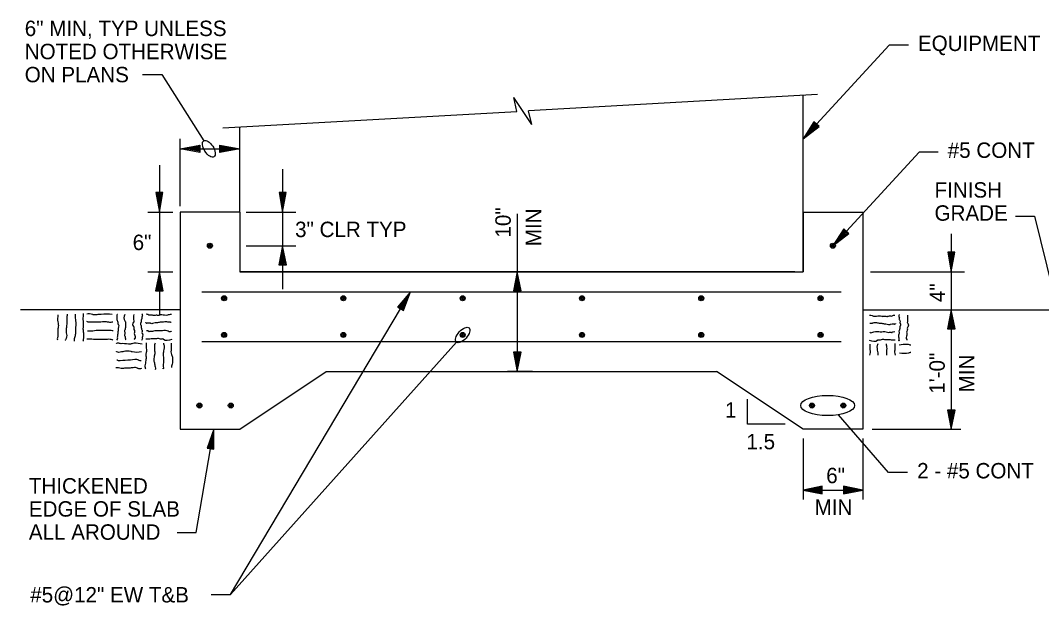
# Model space of a CAD drawing. Extents: x -123486 to -116575, y -107066 to -101122.
# Drawn here: x -118359.2 to -117961.3, y -101555.2 to -101327.3 of the extents above; entities that cross this region are included whole.
import ezdxf

# ---------------------------------------------------------------- set-up
doc = ezdxf.new("R2010")
doc.units = 0
for name, color, linetype in [('G-MARK', 7, 'Continuous'), ('G-TEXT', 7, 'Continuous'), ('Misc CnstDet(22)', 7, 'Continuous'), ('S-FNDN-PILE', 7, 'Continuous')]:
    doc.layers.add(name, color=color, linetype=linetype)

# ---------------------------------------------------------------- blocks, each defined once
blk = doc.blocks.new('ARROW')
at = {"layer": 'S-FNDN-PILE'}
blk.add_lwpolyline([(-0.002083, 0.000367), (-0.002083, -0.000367), (0, 0), (-0.002083, 0.000367), (-0.001983, 0), (-0.002017, -0.000267), (-0.00045, 0.000017), (-0.002017, 0.0003), (-0.001917, 0), (-0.001917, -0.000167), (-0.000833, 0.000017), (-0.001883, 0.0002), (-0.001867, -0.000117), (-0.001217, 0), (-0.001817, 0.0001), (-0.001767, -0.00005), (-0.00155, 0), (-0.002083, 0)], dxfattribs=at)

msp = doc.modelspace()

# ---------------------------------------------------------------- linework, layer by layer
at = {"layer": 'G-MARK'}
for p, q in [((-118296.98, -101399.61), (-118296.98, -101373.44)), ((-118296.98, -101377.28), (-118273.73, -101377.28)), ((-118305, -101383.6), (-118305, -101442.17)), ((-118257.03, -101385.28), (-118257.03, -101432)), ((-118309.54, -101401.97), (-118299.83, -101401.97)), ((-118271.21, -101401.97), (-118251.86, -101401.97)), ((-118165.59, -101402.62), (-118165.59, -101425.21)), ((-117996.47, -101410.39), (-117996.47, -101439.97)), ((-118271.21, -101415.04), (-118251.86, -101415.04)), ((-117996.47, -101411.69), (-117996.47, -101425.21)), ((-118309.5, -101425.21), (-118299.83, -101425.21)), ((-118165.59, -101425.21), (-118165.59, -101463.96)), ((-118027.96, -101425.21), (-117991.3, -101425.21)), ((-117996.47, -101439.97), (-117996.47, -101486.46)), ((-118027.24, -101486.46), (-117992.75, -101486.46)), ((-118054.21, -101510.18), (-118030.96, -101510.18))]:
    msp.add_line(p, q, dxfattribs=at)
for points in [[(-118013.16, -101336.92), (-118020.6, -101336.92), (-118048.96, -101367.72)], [(-118311.57, -101348.3), (-118304.13, -101348.3), (-118287.72, -101374.16)], [(-118001.53, -101378.54), (-118008.97, -101378.54), (-118037.33, -101409.34)], [(-117971.4, -101403.56), (-117963.96, -101403.56), (-117956.81, -101432.45)], [(-118284.8, -101550.89), (-118277.36, -101550.89), (-118211.07, -101439.62)], [(-118284.8, -101550.89), (-118277.36, -101550.89), (-118189.31, -101452.54)], [(-118061.22, -101484.54), (-118075.88, -101484.54), (-118075.88, -101474.83)], [(-118013.46, -101503.38), (-118020.9, -101503.38), (-118040.44, -101480.86)], [(-118298.09, -101526.75), (-118290.65, -101526.75), (-118285.13, -101494.1)]]:
    msp.add_lwpolyline(points, dxfattribs=at)
msp.add_ellipse((-118044.62, -101477.26), major_axis=(-10.49, 0), ratio=0.373805, dxfattribs=at)
at = {"layer": 'G-TEXT'}
for points in [[(-118047.95, -101368.65), (-118049.96, -101366.8), (-118054.21, -101373.42), (-118047.95, -101368.65), (-118049.21, -101367.99), (-118049.85, -101367.23), (-118053.03, -101372.23), (-118048.3, -101368.66), (-118049.38, -101368.18), (-118049.83, -101367.76), (-118052.06, -101371.18), (-118048.91, -101368.77), (-118049.82, -101368.02), (-118051.14, -101370.09), (-118049.35, -101368.7), (-118049.89, -101368.46), (-118050.3, -101369.18), (-118048.96, -101367.72)], [(-118289.29, -101375.85), (-118289.29, -101378.71), (-118296.98, -101377.28), (-118289.29, -101375.85), (-118289.66, -101377.28), (-118289.54, -101378.27), (-118295.24, -101377.22), (-118289.54, -101376.16), (-118289.91, -101377.28), (-118289.91, -101377.9), (-118293.88, -101377.22), (-118290.03, -101376.54), (-118290.1, -101377.71), (-118292.45, -101377.28), (-118290.28, -101376.91), (-118290.47, -101377.47), (-118291.21, -101377.28), (-118289.29, -101377.28)], [(-118281.42, -101378.71), (-118281.42, -101375.85), (-118273.73, -101377.28), (-118281.42, -101378.71), (-118281.05, -101377.28), (-118281.17, -101376.29), (-118275.47, -101377.34), (-118281.17, -101378.4), (-118280.8, -101377.28), (-118280.8, -101376.66), (-118276.83, -101377.34), (-118280.68, -101378.02), (-118280.62, -101376.85), (-118278.26, -101377.28), (-118280.43, -101377.65), (-118280.24, -101377.09), (-118279.5, -101377.28), (-118281.42, -101377.28)], [(-118303.63, -101394.28), (-118306.36, -101394.28), (-118305, -101401.97), (-118303.63, -101394.28), (-118305, -101394.65), (-118305.99, -101394.53), (-118304.94, -101400.23), (-118303.88, -101394.53), (-118305, -101394.9), (-118305.62, -101394.9), (-118304.94, -101398.87), (-118304.26, -101395.02), (-118305.43, -101395.08), (-118305, -101397.44), (-118304.63, -101395.27), (-118305.19, -101395.46), (-118305, -101396.2), (-118305, -101394.28)], [(-118255.66, -101394.28), (-118258.39, -101394.28), (-118257.03, -101401.97), (-118255.66, -101394.28), (-118257.03, -101394.65), (-118258.02, -101394.53), (-118256.97, -101400.23), (-118255.91, -101394.53), (-118257.03, -101394.9), (-118257.65, -101394.9), (-118256.97, -101398.87), (-118256.28, -101395.02), (-118257.46, -101395.08), (-118257.03, -101397.44), (-118256.66, -101395.27), (-118257.21, -101395.46), (-118257.03, -101396.2), (-118257.03, -101394.28)], [(-118036.33, -101410.26), (-118038.34, -101408.42), (-118042.58, -101415.04), (-118036.33, -101410.26), (-118037.59, -101409.61), (-118038.23, -101408.85), (-118041.41, -101413.85), (-118036.68, -101410.28), (-118037.75, -101409.8), (-118038.21, -101409.38), (-118040.44, -101412.8), (-118037.29, -101410.39), (-118038.2, -101409.64), (-118039.52, -101411.71), (-118037.73, -101410.32), (-118038.27, -101410.08), (-118038.68, -101410.8), (-118037.33, -101409.34)], [(-117995.1, -101417.52), (-117997.83, -101417.52), (-117996.47, -101425.21), (-117995.1, -101417.52), (-117996.47, -101417.89), (-117997.46, -101417.77), (-117996.41, -101423.47), (-117995.35, -101417.77), (-117996.47, -101418.14), (-117997.09, -101418.14), (-117996.41, -101422.11), (-117995.72, -101418.27), (-117996.9, -101418.33), (-117996.47, -101420.68), (-117996.1, -101418.51), (-117996.65, -101418.7), (-117996.47, -101419.44), (-117996.47, -101417.52)], [(-118167.08, -101432.65), (-118164.1, -101432.65), (-118165.59, -101425.21), (-118167.08, -101432.65), (-118165.59, -101432.3), (-118164.51, -101432.42), (-118165.66, -101426.82), (-118166.81, -101432.42), (-118165.59, -101432.06), (-118164.92, -101432.06), (-118165.66, -101428.19), (-118166.4, -101431.94), (-118165.12, -101431.88), (-118165.59, -101429.56), (-118166, -101431.7), (-118165.39, -101431.52), (-118165.59, -101430.75), (-118165.59, -101432.65)], [(-118212.24, -101438.92), (-118209.9, -101440.32), (-118207.11, -101432.96), (-118212.24, -101438.92), (-118210.88, -101439.3), (-118210.09, -101439.91), (-118208.02, -101434.37), (-118211.91, -101438.84), (-118210.76, -101439.09), (-118210.22, -101439.4), (-118208.75, -101435.59), (-118211.33, -101438.6), (-118210.29, -101439.15), (-118209.42, -101436.85), (-118210.88, -101438.58), (-118210.31, -101438.7), (-118210.06, -101437.91), (-118211.07, -101439.62)], [(-118164.1, -101456.51), (-118167.08, -101456.51), (-118165.59, -101463.96), (-118164.1, -101456.51), (-118165.59, -101456.87), (-118166.67, -101456.75), (-118165.52, -101462.35), (-118164.37, -101456.75), (-118165.59, -101457.11), (-118166.27, -101457.11), (-118165.52, -101460.98), (-118164.78, -101457.23), (-118166.07, -101457.29), (-118165.59, -101459.61), (-118165.19, -101457.47), (-118165.8, -101457.65), (-118165.59, -101458.42), (-118165.59, -101456.51)], [(-117994.99, -101479.02), (-117997.96, -101479.02), (-117996.47, -101486.46), (-117994.99, -101479.02), (-117996.47, -101479.38), (-117997.56, -101479.26), (-117996.41, -101484.86), (-117995.26, -101479.26), (-117996.47, -101479.62), (-117997.15, -101479.62), (-117996.41, -101483.49), (-117995.66, -101479.74), (-117996.95, -101479.8), (-117996.47, -101482.12), (-117996.07, -101479.98), (-117996.68, -101480.15), (-117996.47, -101480.93), (-117996.47, -101479.02)], [(-118286.47, -101493.88), (-118283.78, -101494.33), (-118283.83, -101486.46), (-118286.47, -101493.88), (-118285.06, -101493.74), (-118284.11, -101494.03), (-118284.17, -101488.1), (-118286.18, -101493.67), (-118285.02, -101493.49), (-118284.41, -101493.6), (-118284.41, -101489.51), (-118285.73, -101493.25), (-118284.56, -101493.38), (-118284.59, -101490.92), (-118285.33, -101493.06), (-118284.75, -101492.97), (-118284.79, -101492.15), (-118285.13, -101494.11)], [(-118046.77, -101511.67), (-118046.77, -101508.69), (-118054.21, -101510.18), (-118046.77, -101511.67), (-118047.13, -101510.18), (-118047.01, -101509.1), (-118052.61, -101510.25), (-118047.01, -101511.4), (-118047.37, -101510.18), (-118047.37, -101509.51), (-118051.24, -101510.25), (-118047.49, -101510.99), (-118047.55, -101509.71), (-118049.87, -101510.18), (-118047.73, -101510.59), (-118047.9, -101509.98), (-118048.68, -101510.18), (-118046.77, -101510.18)], [(-118038.41, -101508.69), (-118038.41, -101511.67), (-118030.97, -101510.18), (-118038.41, -101508.69), (-118038.05, -101510.18), (-118038.17, -101511.26), (-118032.58, -101510.11), (-118038.17, -101508.96), (-118037.81, -101510.18), (-118037.81, -101510.86), (-118033.95, -101510.11), (-118037.7, -101509.37), (-118037.64, -101510.66), (-118035.31, -101510.18), (-118037.46, -101509.78), (-118037.28, -101510.38), (-118036.51, -101510.18), (-118038.41, -101510.18)]]:
    msp.add_lwpolyline(points, dxfattribs=at)
for centre, major_axis in [((-118285.75, -101377.28), (1.99, -3.14)), ((-118186.84, -101449.8), (2.48, 2.77))]:
    msp.add_ellipse(centre, major_axis=major_axis, ratio=0.483333, dxfattribs=at)
at = {"layer": 'Misc CnstDet(22)'}
for p, q in [((-118165.77, -101362.71), (-118166.89, -101357.31)), ((-118159.88, -101367.85), (-118166.89, -101357.31)), ((-118161.18, -101362.4), (-118048.51, -101356.01)), ((-118054.21, -101425.21), (-118054.21, -101356.38)), ((-118280.3, -101369.16), (-118165.77, -101362.71)), ((-118165.77, -101362.71), (-118165.77, -101362.71)), ((-118159.88, -101367.85), (-118161.18, -101362.46)), ((-118161.18, -101362.46), (-118161.18, -101362.46)), ((-118273.73, -101401.97), (-118273.73, -101368.79)), ((-118273.73, -101377.28), (-118273.73, -101377.28)), ((-118273.73, -101401.97), (-118296.98, -101401.97)), ((-118296.98, -101401.97), (-118296.98, -101428.12)), ((-118273.73, -101401.97), (-118273.73, -101425.21)), ((-118054.21, -101401.97), (-118030.96, -101401.97)), ((-118054.21, -101401.97), (-118054.21, -101425.21)), ((-118030.96, -101401.97), (-118030.96, -101428.12)), ((-118273.73, -101425.21), (-118054.21, -101425.21)), ((-118057.45, -101425.21), (-118273.73, -101425.21)), ((-118158.24, -101425.21), (-118169.31, -101425.21)), ((-118296.98, -101428.12), (-118296.98, -101486.46)), ((-118030.96, -101428.12), (-118030.96, -101486.46)), ((-118288.55, -101432.96), (-118039.4, -101432.96)), ((-118296.98, -101439.97), (-118359.18, -101439.97)), ((-118030.96, -101439.97), (-117941.11, -101439.97)), ((-118288.55, -101452.33), (-118039.4, -101452.33)), ((-118273.73, -101486.46), (-118239.98, -101463.96)), ((-118239.98, -101463.96), (-118087.97, -101463.96)), ((-118159.63, -101463.96), (-118169.31, -101463.96)), ((-118054.21, -101486.46), (-118087.97, -101463.96)), ((-118296.98, -101486.46), (-118273.73, -101486.46)), ((-118030.96, -101486.46), (-118054.21, -101486.46)), ((-118054.21, -101490.18), (-118054.21, -101513.9)), ((-118030.96, -101490.18), (-118030.96, -101513.9))]:
    msp.add_line(p, q, dxfattribs=at)
for centre, radius in [((-118285.36, -101415.04), 0.969), ((-118285.36, -101415.04), 0.581), ((-118285.36, -101415.04), 0.176), ((-118042.58, -101415.04), 0.969), ((-118042.58, -101415.04), 0.581), ((-118042.58, -101415.04), 0.176), ((-118279.83, -101435.5), 0.969), ((-118279.83, -101435.5), 0.581), ((-118279.83, -101435.5), 0.176), ((-118233.34, -101435.5), 0.969), ((-118233.34, -101435.5), 0.581), ((-118233.34, -101435.5), 0.176), ((-118186.85, -101435.5), 0.969), ((-118186.85, -101435.5), 0.581), ((-118186.85, -101435.5), 0.176), ((-118140.35, -101435.5), 0.969), ((-118140.35, -101435.5), 0.581), ((-118140.35, -101435.5), 0.176), ((-118093.86, -101435.5), 0.969), ((-118093.86, -101435.5), 0.581), ((-118093.86, -101435.5), 0.176), ((-118047.37, -101435.5), 0.969), ((-118047.37, -101435.5), 0.581), ((-118047.37, -101435.5), 0.176), ((-118279.83, -101449.79), 0.969), ((-118279.83, -101449.79), 0.581), ((-118279.83, -101449.79), 0.176), ((-118233.34, -101449.79), 0.969), ((-118233.34, -101449.79), 0.581), ((-118233.34, -101449.79), 0.176), ((-118186.85, -101449.79), 0.969), ((-118186.85, -101449.79), 0.581), ((-118186.85, -101449.79), 0.176), ((-118140.35, -101449.79), 0.969), ((-118140.35, -101449.79), 0.581), ((-118140.35, -101449.79), 0.176), ((-118093.86, -101449.79), 0.969), ((-118093.86, -101449.79), 0.581), ((-118093.86, -101449.79), 0.176), ((-118047.37, -101449.79), 0.969), ((-118047.37, -101449.79), 0.581), ((-118047.37, -101449.79), 0.176), ((-118289.43, -101477.29), 0.969), ((-118289.43, -101477.29), 0.581), ((-118289.43, -101477.29), 0.176), ((-118277.21, -101477.29), 0.969), ((-118277.21, -101477.29), 0.581), ((-118277.21, -101477.29), 0.176), ((-118050.73, -101477.29), 0.969), ((-118050.73, -101477.29), 0.581), ((-118050.73, -101477.29), 0.176), ((-118038.51, -101477.29), 0.969), ((-118038.51, -101477.29), 0.581), ((-118038.51, -101477.29), 0.176)]:
    msp.add_circle(centre, radius, dxfattribs=at)
for points in [[(-118344.6, -101441.95), (-118344.6, -101444.68), (-118344.42, -101445.74), (-118344.54, -101447.41), (-118344.6, -101449.83), (-118344.6, -101450.57), (-118344.79, -101450.95), (-118344.79, -101451.69)], [(-118340.94, -101441.64), (-118341.13, -101443.69), (-118341.19, -101446.17), (-118341.38, -101447.72), (-118341.38, -101448.96), (-118341.38, -101451.13), (-118341.63, -101451.94), (-118341.56, -101451.94)], [(-118337.84, -101441.64), (-118337.78, -101443.75), (-118337.66, -101444.31), (-118337.66, -101446.73), (-118337.78, -101449.4), (-118337.84, -101450.08), (-118338.28, -101451.75), (-118338.28, -101452.19)], [(-118334.74, -101441.46), (-118334.8, -101443.75), (-118334.74, -101446.17), (-118334.8, -101447.35), (-118334.62, -101449.02), (-118334.56, -101450.45), (-118334.74, -101451.81), (-118334.8, -101452.25)], [(-118323.39, -101441.77), (-118327.73, -101441.77), (-118329.41, -101441.89), (-118330.77, -101441.89), (-118331.14, -101441.77), (-118333.32, -101441.64)], [(-118321.35, -101441.77), (-118321.47, -101441.77), (-118321.6, -101442.51), (-118321.6, -101443.75), (-118321.22, -101445.24), (-118321.22, -101445.49), (-118321.1, -101445.61), (-118321.1, -101447.85), (-118321.1, -101448.34), (-118321.22, -101448.59), (-118321.22, -101449.46), (-118321.35, -101449.58), (-118321.35, -101450.14), (-118321.47, -101450.64), (-118321.47, -101451.38), (-118321.6, -101451.5), (-118321.47, -101451.63), (-118321.47, -101451.88)], [(-118318.5, -101441.77), (-118318.5, -101444.25), (-118318.37, -101444.37), (-118318.25, -101446.61), (-118318.25, -101446.98), (-118318.37, -101446.98), (-118318.37, -101447.72), (-118318.5, -101447.85), (-118318.5, -101449.09), (-118318.5, -101450.26), (-118318.37, -101450.39), (-118318.37, -101451.13), (-118318.25, -101451.13), (-118318.25, -101451.38), (-118318.12, -101451.75)], [(-118315.02, -101441.77), (-118315.02, -101444.37), (-118315.02, -101444.75), (-118315.15, -101444.87), (-118315.15, -101446.48), (-118315.02, -101446.61), (-118315.02, -101447.23), (-118314.78, -101448.09), (-118314.78, -101449.58), (-118314.78, -101451.26), (-118314.9, -101451.38), (-118314.78, -101451.38)], [(-118311.86, -101441.52), (-118311.74, -101441.89), (-118311.74, -101442.51), (-118311.86, -101442.64), (-118311.86, -101443.51), (-118311.99, -101443.63), (-118312.11, -101444.62), (-118312.11, -101444.87), (-118312.23, -101444.99), (-118312.23, -101445.99), (-118312.11, -101446.23), (-118312.11, -101446.98), (-118311.99, -101447.23), (-118311.99, -101447.6), (-118311.86, -101447.72), (-118311.74, -101449.21), (-118311.61, -101449.33), (-118311.61, -101450.26), (-118311.61, -101450.39), (-118311.74, -101450.64), (-118311.74, -101451.5), (-118311.86, -101451.75), (-118311.74, -101451.75), (-118311.74, -101451.63)], [(-118300.27, -101441.83), (-118301.26, -101441.89), (-118301.88, -101442.14), (-118302.99, -101442.14), (-118305.1, -101442.14), (-118305.47, -101442.27), (-118306.03, -101442.14), (-118307.27, -101442.27), (-118307.65, -101442.14), (-118309.13, -101442.02), (-118309.63, -101441.77), (-118310.13, -101441.77)], [(-118028.32, -101442.14), (-118027.32, -101442.2), (-118026.7, -101442.45), (-118025.59, -101442.45), (-118023.48, -101442.45), (-118023.11, -101442.58), (-118022.55, -101442.45), (-118021.31, -101442.58), (-118020.94, -101442.45), (-118019.45, -101442.33), (-118018.95, -101442.08), (-118018.45, -101442.08)], [(-118016.72, -101441.83), (-118016.84, -101442.2), (-118016.84, -101442.82), (-118016.72, -101442.95), (-118016.72, -101443.82), (-118016.59, -101443.94), (-118016.47, -101444.93), (-118016.47, -101445.18), (-118016.35, -101445.3), (-118016.35, -101446.3), (-118016.47, -101446.54), (-118016.47, -101447.29), (-118016.59, -101447.54), (-118016.59, -101447.91), (-118016.72, -101448.03), (-118016.84, -101449.52), (-118016.97, -101449.64), (-118016.97, -101450.57), (-118016.97, -101450.7), (-118016.84, -101450.95), (-118016.84, -101451.81), (-118016.72, -101452.06), (-118016.84, -101452.06), (-118016.84, -101451.94)], [(-118013.56, -101442.08), (-118013.56, -101444.68), (-118013.56, -101445.06), (-118013.43, -101445.18), (-118013.43, -101446.79), (-118013.56, -101446.92), (-118013.56, -101447.54), (-118013.8, -101448.4), (-118013.8, -101449.89), (-118013.8, -101451.57), (-118013.68, -101451.69), (-118013.8, -101451.69)], [(-118323.15, -101444.75), (-118324.76, -101444.87), (-118325.69, -101444.68), (-118326.56, -101444.68), (-118329.16, -101444.81), (-118331.77, -101444.81), (-118332.76, -101444.75), (-118333.25, -101444.5)], [(-118300.39, -101444.99), (-118300.64, -101444.87), (-118301.38, -101444.87), (-118301.75, -101444.75), (-118303.37, -101444.75), (-118303.99, -101444.87), (-118304.73, -101444.87), (-118306.03, -101445.12), (-118306.65, -101445.12), (-118307.65, -101445.37), (-118308.27, -101445.37), (-118308.51, -101445.24), (-118310, -101445.24), (-118309.88, -101445.24), (-118310.37, -101445.12), (-118310.37, -101444.99), (-118310.37, -101445.12)], [(-118028.19, -101445.3), (-118027.94, -101445.18), (-118027.2, -101445.18), (-118026.83, -101445.06), (-118025.21, -101445.06), (-118024.59, -101445.18), (-118023.85, -101445.18), (-118022.55, -101445.43), (-118021.93, -101445.43), (-118020.94, -101445.68), (-118020.32, -101445.68), (-118020.07, -101445.55), (-118018.58, -101445.55), (-118018.7, -101445.55), (-118018.21, -101445.43), (-118018.21, -101445.3), (-118018.21, -101445.43)], [(-118323.15, -101451.81), (-118323.39, -101451.69), (-118325.19, -101451.5), (-118327.92, -101451.5), (-118330.71, -101451.5), (-118333.32, -101451.44)], [(-118323.08, -101448.28), (-118323.33, -101448.16), (-118324.2, -101448.03), (-118326.74, -101448.09), (-118329.66, -101448.09), (-118332.14, -101448.34), (-118332.88, -101448.28), (-118333.07, -101448.28)], [(-118300.14, -101451.5), (-118303.37, -101451.5), (-118303.49, -101451.38), (-118304.11, -101451.38), (-118304.61, -101451.38), (-118305.35, -101451.13), (-118306.16, -101451.26), (-118307.77, -101451.26), (-118308.76, -101451.38), (-118310.25, -101451.38)], [(-118300.39, -101448.34), (-118300.51, -101448.47), (-118302, -101448.22), (-118304.48, -101448.22), (-118306.78, -101448.22), (-118307.77, -101448.47), (-118308.89, -101448.47), (-118309.13, -101448.47), (-118309.13, -101448.34), (-118309.13, -101448.47), (-118309.13, -101448.34), (-118309.38, -101448.34), (-118309.51, -101448.22), (-118310, -101448.22)], [(-118028.44, -101451.81), (-118025.21, -101451.81), (-118025.09, -101451.69), (-118024.47, -101451.69), (-118023.97, -101451.69), (-118023.23, -101451.44), (-118022.42, -101451.57), (-118020.81, -101451.57), (-118019.82, -101451.69), (-118018.33, -101451.69)], [(-118028.19, -101448.65), (-118028.07, -101448.78), (-118026.58, -101448.53), (-118024.1, -101448.53), (-118021.8, -101448.53), (-118020.81, -101448.78), (-118019.7, -101448.78), (-118019.45, -101448.78), (-118019.45, -101448.65), (-118019.45, -101448.78), (-118019.45, -101448.65), (-118019.2, -101448.65), (-118019.08, -101448.53), (-118018.58, -101448.53)], [(-118311.8, -101453.36), (-118314.9, -101453.05), (-118315.77, -101453.24), (-118316.33, -101453.36), (-118319.43, -101453.18), (-118320.29, -101453.18), (-118321.41, -101452.99), (-118321.53, -101453.05), (-118321.91, -101452.99)], [(-118310.13, -101452.81), (-118310.13, -101454.98), (-118310.13, -101456.65), (-118310.25, -101457.08), (-118310.25, -101457.89), (-118310.25, -101459.32), (-118310.44, -101460.25), (-118310.44, -101460.8), (-118310.68, -101461.8), (-118310.62, -101462.42), (-118310.5, -101463.04)], [(-118306.72, -101452.93), (-118306.9, -101453.67), (-118306.9, -101455.91), (-118306.9, -101457.58), (-118307.03, -101457.89), (-118307.15, -101459.01), (-118307.21, -101459.75), (-118307.03, -101460.31), (-118306.78, -101461.8), (-118306.59, -101462.73), (-118306.65, -101463.35)], [(-118303.49, -101452.99), (-118303.18, -101454.17), (-118303.3, -101455.41), (-118303.49, -101456.46), (-118303.49, -101458.39), (-118303.49, -101460.68), (-118303.49, -101462.6), (-118303.49, -101462.85), (-118303.55, -101462.97), (-118303.55, -101462.73)], [(-118300.45, -101453.05), (-118300.45, -101455.16), (-118300.51, -101456.34), (-118300.33, -101457.39), (-118299.89, -101458.82), (-118299.89, -101459.5), (-118299.89, -101460.25), (-118300.27, -101461.98), (-118300.33, -101462.48)], [(-118028.13, -101453.36), (-118028.13, -101455.47), (-118028.07, -101456.65), (-118028.25, -101457.64)], [(-118025.09, -101453.3), (-118025.4, -101454.48), (-118025.28, -101455.72), (-118025.09, -101456.77), (-118025.09, -101457.64)], [(-118021.87, -101453.24), (-118021.68, -101453.98), (-118021.68, -101456.22), (-118021.68, -101457.64)], [(-118018.45, -101453.12), (-118018.45, -101455.29), (-118018.45, -101456.96), (-118018.33, -101457.39), (-118018.33, -101457.64)], [(-118016.78, -101453.67), (-118013.68, -101453.36), (-118012.81, -101453.55), (-118012.25, -101453.67), (-118012.19, -101453.67)], [(-118311.99, -101456.4), (-118315.64, -101456.4), (-118316.08, -101456.28), (-118318.87, -101456.22), (-118319.74, -101456.4), (-118321.66, -101456.34), (-118321.72, -101456.28)], [(-118312.17, -101459.87), (-118312.92, -101459.75), (-118313.1, -101459.63), (-118316.33, -101459.56), (-118320.29, -101459.87), (-118320.98, -101459.87), (-118321.41, -101459.63), (-118321.66, -101459.63)], [(-118016.59, -101456.71), (-118012.94, -101456.71), (-118012.5, -101456.59), (-118012.19, -101456.53)], [(-118311.99, -101462.91), (-118313.35, -101462.85), (-118313.54, -101462.73), (-118315.21, -101462.54), (-118316.82, -101462.73), (-118318.12, -101462.73), (-118319.92, -101462.85), (-118320.91, -101462.66), (-118322.03, -101462.6)]]:
    msp.add_spline(points, degree=3, dxfattribs=at)

# ---------------------------------------------------------------- block references
at = {"layer": 'G-TEXT', "xscale": 3571.703056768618, "yscale": 4058.0876675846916, "rotation": 90}
for p in [(-118257.03, -101415.02), (-118305, -101425.19), (-117996.47, -101439.97)]:
    msp.add_blockref('ARROW', p, dxfattribs=at)

# ---------------------------------------------------------------- texts
at = {"layer": 'G-MARK'}
for s, p in [('6" MIN, TYP UNLESS', (-118357.5, -101333.38)), ('NOTED OTHERWISE', (-118357.5, -101342.38)), ('ON PLANS', (-118357.5, -101351.38)), ('FINISH', (-118002.97, -101396.3)), ('GRADE', (-118002.97, -101405.3)), ('2 - #5 CONT', (-118009.74, -101505.66))]:
    msp.add_text(s, height=6, dxfattribs=at).set_placement(p)
at = {"layer": 'Misc CnstDet(22)'}
for s, p in [('EQUIPMENT', (-118009.44, -101339.2)), ('#5 CONT', (-117997.82, -101380.82)), ('1', (-118084.62, -101482.02)), ('1.5', (-118076.26, -101494.32)), ('6"', (-118045.17, -101507.53)), ('THICKENED', (-118355.89, -101511.55)), ('EDGE OF SLAB', (-118355.89, -101520.55)), ('MIN', (-118049.7, -101519.87)), ('ALL AROUND', (-118355.89, -101529.55)), ('#5@12" EW T&B', (-118355.35, -101553.98))]:
    msp.add_text(s, height=6, dxfattribs=at).set_placement(p)
for s, rotation, p in [('10"', 90, (-118168.11, -101411.86)), ('MIN', 90, (-118156.25, -101415.23)), ('3" CLR TYP', 360, (-118252.15, -101411.67)), ('6"', 360, (-118315.44, -101416.72)), ('4"', 90, (-117998.84, -101437.01)), ('1\'-0"', 90, (-117998.99, -101472.68)), ('MIN', 90, (-117987.43, -101472.15))]:
    msp.add_text(s, height=6, rotation=rotation, dxfattribs=at).set_placement(p)

doc.saveas('drawing.dxf')
